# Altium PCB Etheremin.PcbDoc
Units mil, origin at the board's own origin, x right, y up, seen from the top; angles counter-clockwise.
Board outline 6000 x 4000 mil, 2 copper layers (Top Layer, Bottom Layer); 48 components, 40 nets, 135 pads, 0 vias.
Unrouted connection lines stored in the file: 90.
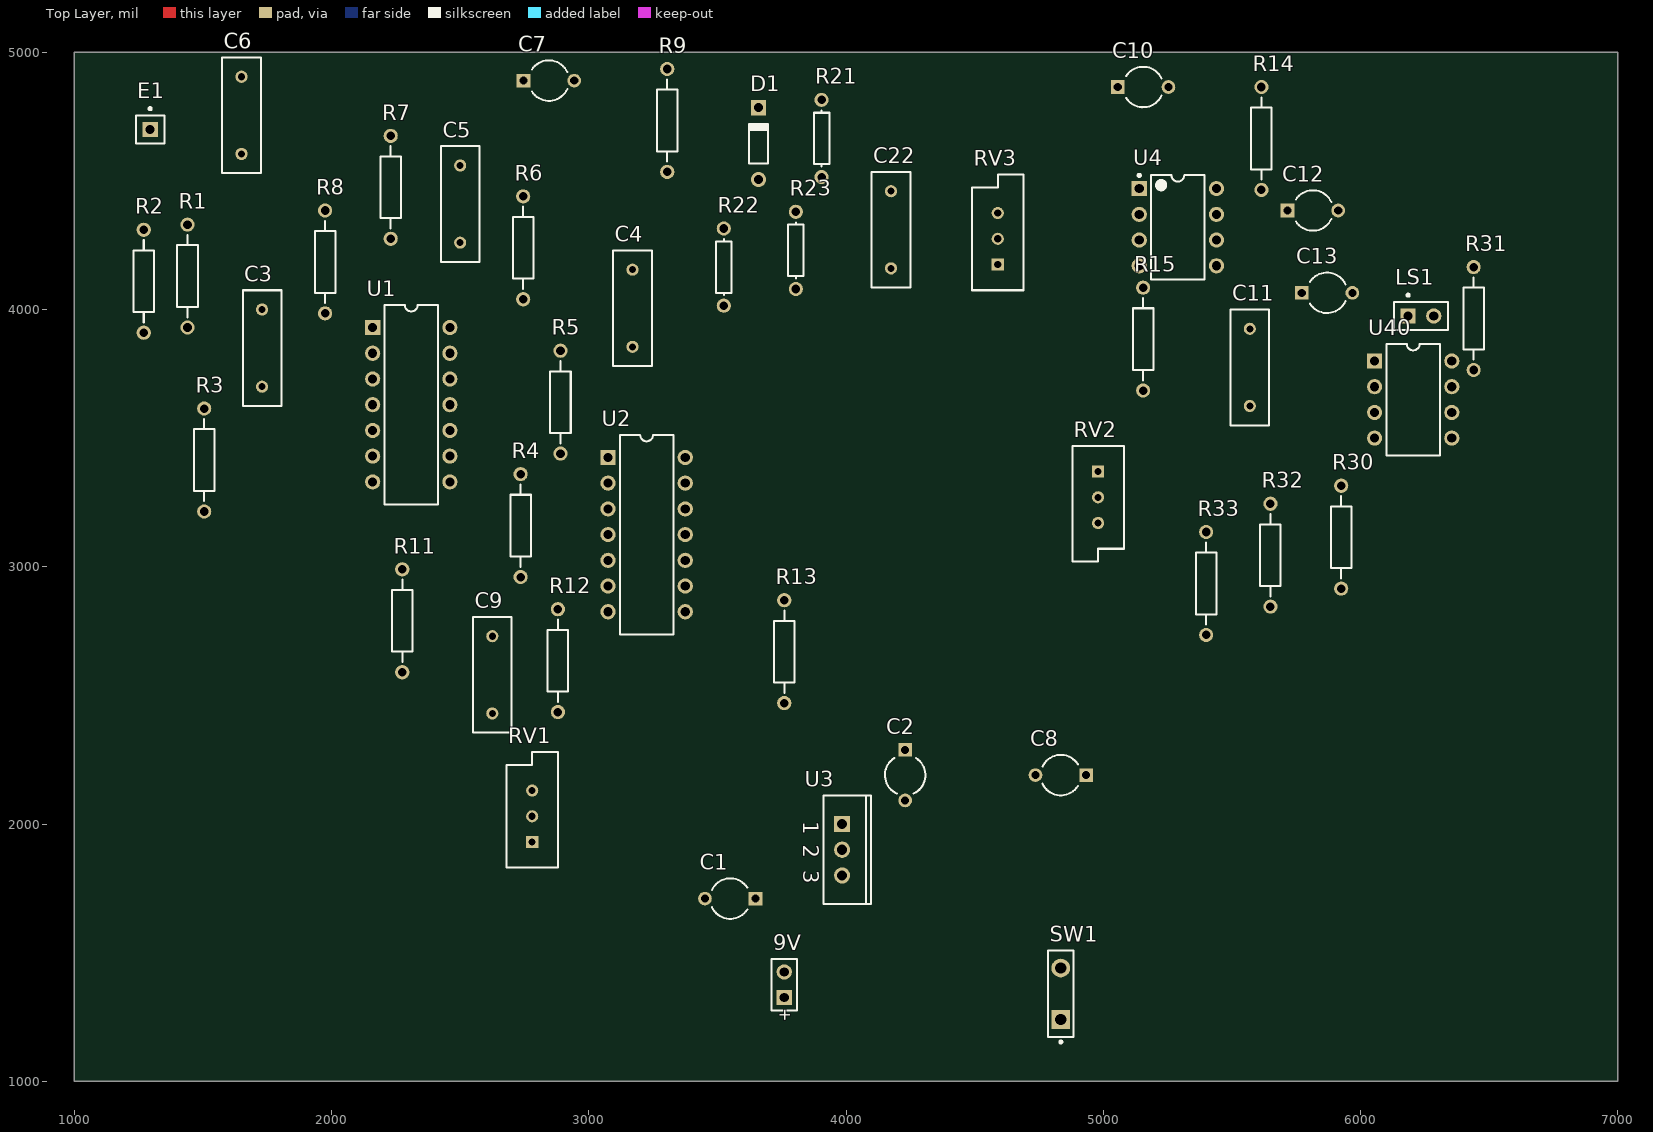
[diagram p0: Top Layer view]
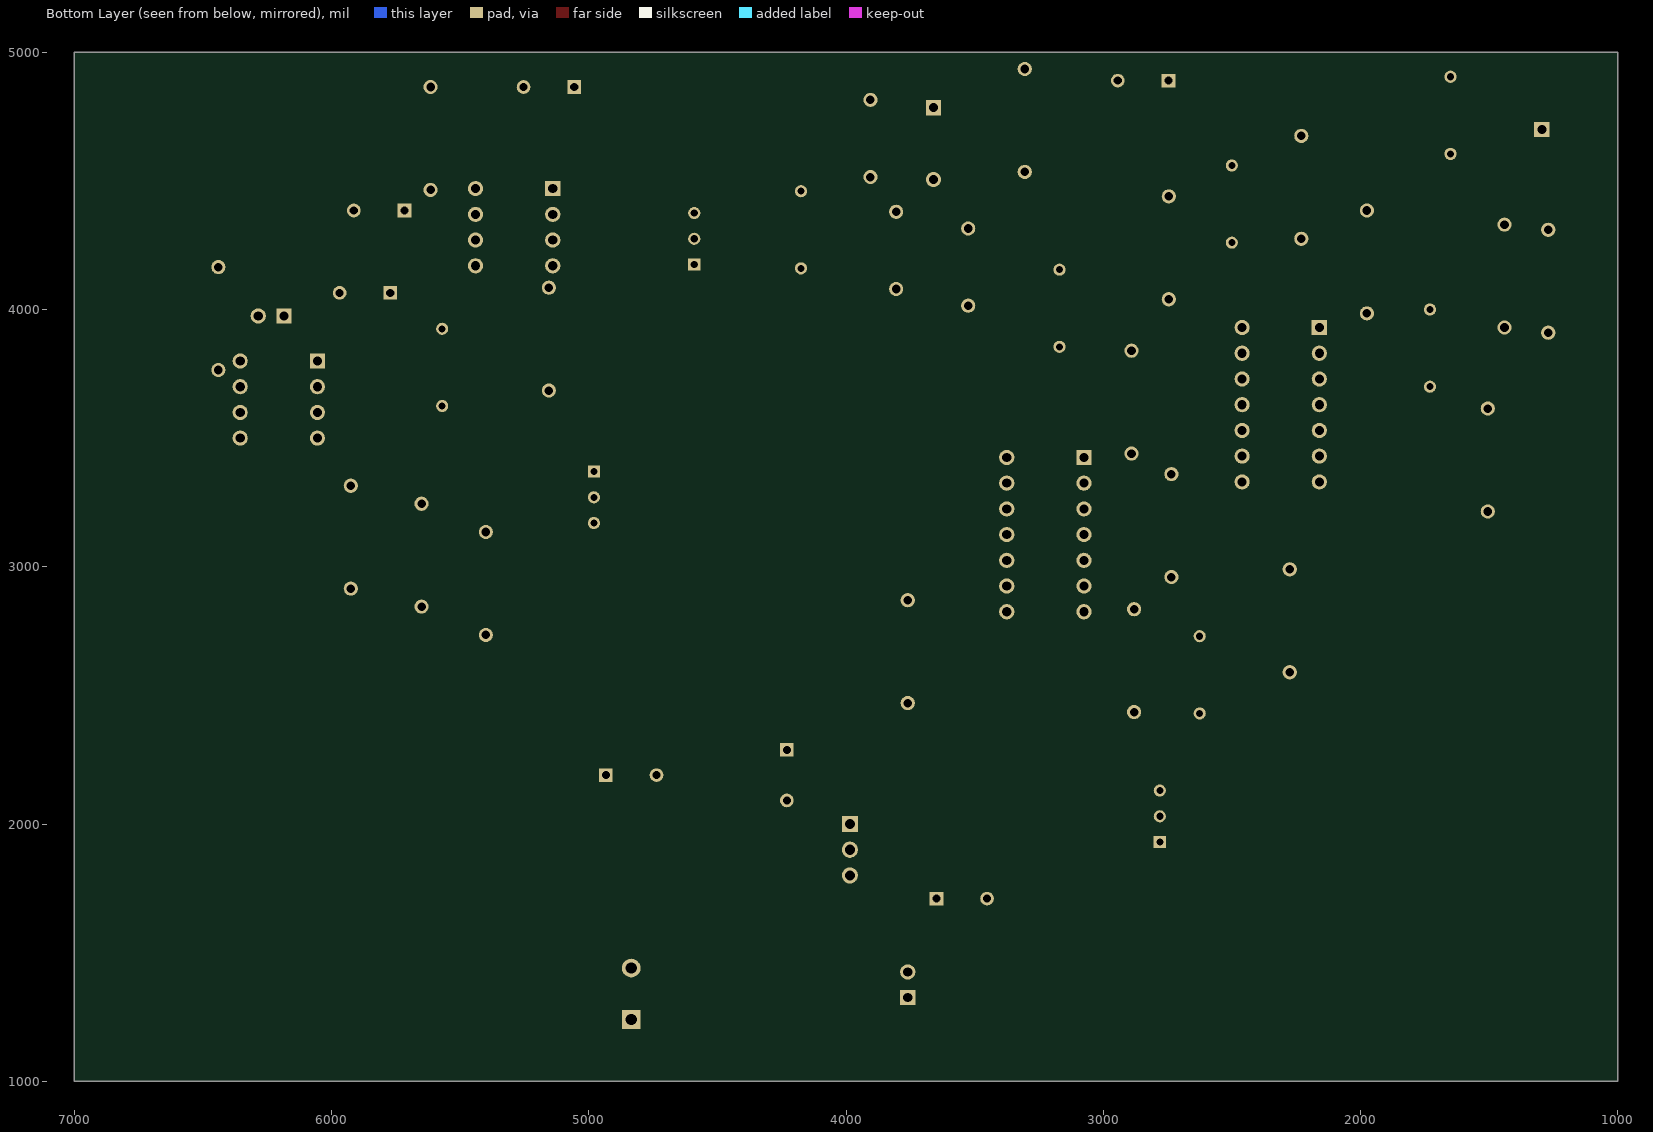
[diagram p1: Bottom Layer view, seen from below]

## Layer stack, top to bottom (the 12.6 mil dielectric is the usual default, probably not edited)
Top Layer: signal copper 1.4
Dielectric: dielectric 12.6, FR-4, Dk 4.8
Bottom Layer: signal copper 1.4

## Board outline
1000,1000 7000,1000 7000,5000 1000,5000

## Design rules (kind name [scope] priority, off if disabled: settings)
Clearance [All] p1: gap=10
PolygonConnect [All] p1: connectstyle=Relief reliefconductorwidth=10 reliefentries=4 polygonreliefangle="90 Angle" airgapwidth=10
RoomDefinition Etheremin [InComponentClass('Etheremin')] p1: confinementstyle=ConfineIn formatcopy=TRUE lockcomponents=FALSE outline 565,65 12140,65 12140,965 565,965
RoutingVias [All] p1: holewidth=28 width=50 viastyle="Through Hole" minholewidth=28 minwidth=50 maxholewidth=28 maxwidth=50
SilkscreenOverComponentPads [All] p1: minsilkscreentomaskgap=10
SolderMaskExpansion [All] p1: expansion=4
Width [All] p1: maxlimit=10 minlimit=10 preferedwidth=10
27 further rules are at their usual default settings.

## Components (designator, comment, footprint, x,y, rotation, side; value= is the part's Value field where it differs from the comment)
9V "Battery" BAT-2 3760,1375 r90 top
C1 "" CAPR5-4X5 3550,1710 r180 top
C2 "" CAPR5-4X5 4230,2190 r270 top
C3 "" RAD-0.3 1730,3850 r90 top
C4 "Cap" RAD-0.3 3170,4005 r90 top
C5 "" RAD-0.3 2500,4410 r90 top
C6 "" RAD-0.3 1650,4755 r90 top
C7 "" CAPR5-4X5 2845,4890 r0 top
C8 "" CAPR5-4X5 4835,2190 r180 top
C9 "" RAD-0.3 2625,2580 r90 top
C10 "" CAPR5-4X5 5155,4865 r0 top
C11 "" RAD-0.3 5570,3775 r90 top
C12 "" CAPR5-4X5 5815,4385 r0 top
C13 "" CAPR5-4X5 5870,4065 r0 top
C22 "Cap" RAD-0.3 4175,4310 r90 top
D1 "Diode 1N4448" DO-35 3660,4645 r90 top
E1 "Antenna" PIN1 1295,4700 r0 top
LS1 "Speaker" PIN2 6185,3975 r0 top
R1 "" AXIAL-0.4 1440,4130 r90 top
R2 "" AXIAL-0.4 1270,4110 r90 top
R3 "" AXIAL-0.4 1505,3415 r90 top
R4 "" AXIAL-0.4 2735,3160 r90 top
R5 "" AXIAL-0.4 2890,3640 r90 top
R6 "" AXIAL-0.4 2745,4240 r90 top
R7 "" AXIAL-0.4 2230,4475 r90 top
R8 "" AXIAL-0.4 1975,4185 r90 top
R9 "" AXIAL-0.4 3305,4735 r90 top
R11 "" AXIAL-0.4 2275,2790 r90 top
R12 "" AXIAL-0.4 2880,2635 r90 top
R13 "" AXIAL-0.4 3760,2670 r270 top
R14 "" AXIAL-0.4 5615,4665 r270 top
R15 "" AXIAL-0.4 5155,3885 r90 top
R21 "Res1" AXIAL-0.3 3905,4665 r270 top
R22 "Res1" AXIAL-0.3 3525,4165 r90 top
R23 "Res1" AXIAL-0.3 3805,4230 r90 top
R30 "" AXIAL-0.4 5925,3115 r270 top
R31 "" AXIAL-0.4 6440,3965 r90 top
R32 "" AXIAL-0.4 5650,3045 r90 top
R33 "" AXIAL-0.4 5400,2935 r90 top
RV1 "" VR5 2780,2030 r90 top
RV2 "" VR5 4980,3270 r270 top
RV3 "" VR5 4590,4275 r90 top
SW1 "On-Off" SPST-2 4835,1340 r90 top
U1 "SN74LS04N" N014 2310,3630 r270 top
U2 "SN74LS04N" N014 3225,3125 r270 top
U3 "LM317KC" KC03 3985,1900 r270 top
U4 "LM386N-3" N08E 5290,4320 r0 top
U40 "LM193N" DIP8 6205,3650 r270 top

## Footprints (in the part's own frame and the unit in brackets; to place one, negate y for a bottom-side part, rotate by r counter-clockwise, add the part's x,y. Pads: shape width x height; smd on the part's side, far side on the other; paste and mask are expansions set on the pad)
AXIAL-0.3 [mm] "Axial Device, Thru-Hole; 2 Leads; 0.3 in Pin Spacing"
  round 1.4 hole 0.85: 1(-3.81,0) 2(3.81,0)
  silkscreen extent -2.77,-0.76 2.77,0.76
AXIAL-0.4 [mm] "Axial Device, Thru-Hole; 2 Leads; 0.4 in Pin Spacing"
  round 1.4 hole 0.85: 1(-5.08,0) 2(5.08,0)
  silkscreen extent -4.06,-1.02 4.06,1.02
BAT-2 [mm] "Battery; 2 Leads"
  rect 1.5x1.5 hole 0.9: 1(-1.27,0)
  round 1.5 hole 0.9: 2(1.27,0)
  silkscreen extent -2.54,-1.27 2.54,1.27
CAPR5-4X5 [mm] "Capacitor; 2 Leads"
  rect 1.35x1.35 hole 0.8: 1(-2.5,0)
  round 1.35 hole 0.8: 2(2.5,0)
  silkscreen extent -1.69,-2 1.82,2
DIP8 [mm] "DIP; 8 Leads; Row Spacing 7.62 mm; Pitch 2.54 mm"
  rect 1.5x1.5 hole 0.9: 1(-3.81,-3.81)
  round 1.5 hole 0.9: 2(-1.27,-3.81) 3(1.27,-3.81) 4(3.81,-3.81) 5(3.81,3.81) 6(1.27,3.81) 7(-1.27,3.81) 8(-3.81,3.81)
  silkscreen extent -5.5,-2.65 5.5,2.65
DO-35 [mm] "Diode, Axial; Body 3.8 x 1.9 mm (LxDia. max), Lead Dia. 0.53 mm (max)"
  round 1.5 hole 0.9: 1(-3.55,0)
  rect 1.5x1.5 hole 0.9: 2(3.55,0)
  silkscreen extent -1.95,-0.95 2.05,0.95
KC03 [mm] "TO, Thru-Hole, Vertical, Heatsink Mounted; 3 In-Line Leads; Pitch 2.54 mm"
  rect 1.6x1.6 hole 1: 1(-2.54,0)
  round 1.6 hole 1: 2(0,0) 3(2.54,0)
  silkscreen extent -5.35,-1.85 5.35,2.85
N08E [mm] "DIP, 8-Leads, Row Spacing 7.62mm, Pitch 2.54mm, Body 9.91x6.35mm"
  rect 1.5x1.5 hole 0.9: 1(-3.81,3.81)
  round 1.5 hole 0.9: 2(-3.81,1.27) 3(-3.81,-1.27) 4(-3.81,-3.81) 5(3.81,-3.81) 6(3.81,-1.27) 7(3.81,1.27) 8(3.81,3.81)
  silkscreen extent -3.93,-5.15 2.65,5.23, body extent -3.6,-5.15 3.6,5.15, height 5.34
N014 [mm] "DIP; 14 Leads; Row Spacing 7.62 mm; Pitch 2.54 mm"
  rect 1.5x1.5 hole 0.9: 1(-7.62,-3.81)
  round 1.5 hole 0.9: 2(-5.08,-3.81) 3(-2.54,-3.81) 4(0,-3.81) 5(2.54,-3.81) 6(5.08,-3.81) 7(7.62,-3.81) 8(7.62,3.81) 9(5.08,3.81) 10(2.54,3.81) 11(0,3.81) 12(-2.54,3.81) 13(-5.08,3.81) 14(-7.62,3.81)
  silkscreen extent -9.85,-2.65 9.85,2.65
PIN1 [mm] "Generic Antenna; 1 Lead"
  rect 1.5x1.5 hole 0.9: 1(0,0)
  silkscreen extent -1.4,-1.4 1.4,2.17
PIN2 [mm] "Photosensitive Diode; 2 Leads"
  rect 1.5x1.5 hole 0.9: 1(0,0)
  round 1.5 hole 0.9: 2(2.54,0)
  silkscreen extent -1.4,-1.4 3.94,2.17
RAD-0.3 [mm] "Radial Cap, Thru-Hole; 2 Leads; 0.3 in Pin Spacing"
  round 1.2 hole 0.7: 1(-3.81,0) 2(3.81,0)
  silkscreen extent -5.71,-1.91 5.71,1.91
SPST-2 [mm] "Switch; 2 Leads"
  rect 1.85x1.85 hole 1.1: 1(-2.54,0)
  round 1.85 hole 1.1: 2(2.54,0)
  silkscreen extent -4.89,-1.27 4.28,1.27
VR5 [mm] "Thru-Hole; 3 Leads"
  rect 1.2x1.2 hole 0.7: 1(-2.54,0)
  round 1.2 hole 0.7: 2(0,0) 3(2.54,0)
  silkscreen extent -5.08,-2.54 6.35,2.54

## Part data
9V: "Multicell Battery"
C1 C2 C7 C8 C10 C12 C13: library part Cap2, "Capacitor"
C3 C5 C6 C9 C11: library part Cap, "Capacitor"
C4 C22: "Capacitor"
D1: "High Conductance Fast Diode"
E1: "Generic Antenna"
LS1: "Loudspeaker"
R1 R2 R3 R4 R5 R6 R7 R8 R9 R11 R12 R13 R14 R15 R30 R31 R32 R33: library part Res2, "Resistor"
R21 R22 R23: "Resistor"
RV1 RV2 RV3: library part RPot, "Potentiometer"
SW1: library part SW-PB, "Switch"
U1 U2: "Hex Inverter"
U3: "3-Terminal Adjustable Regulator"
U4: "Low Voltage Audio Power Amplifier"
U40: "Low-Power Dual Voltage Comparator"

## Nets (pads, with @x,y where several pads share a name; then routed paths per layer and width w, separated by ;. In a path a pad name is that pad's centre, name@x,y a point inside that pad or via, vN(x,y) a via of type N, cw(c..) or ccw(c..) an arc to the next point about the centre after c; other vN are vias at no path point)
GND: 9V.2 C1.2 C2.2 C5.1 C8.2 C12.2 C22.1 LS1.2 R13.2 R15.2 R22.1 R23.1 R32.1 RV3.1 U1.7 U2.7 U2.9 U3.1 U4.2 U4.4 U40.8
Net9V_1: 9V.1 SW1.1
NetC1_1: C1.1 SW1.2 U3.3
NetC3_1: C3.1 U1.4 U1.5
NetC3_2: C3.2 E1.1 R1.2 R2.2
NetC4_1: C4.1 R5.1 U1.8
NetC4_2: C4.2 R6.1
NetC5_2: C5.2 R6.2 R7.2
NetC6_1: C6.1 R7.1 R8.2 U1.11 U1.13
NetC6_2: C6.2 C7.1 R8.1 U1.10 U1.12
NetC7_2: C7.2 R9.2
NetC8_1: C8.1 RV2.3
NetC9_1: C9.1 R11.1 RV1.1 RV1.3
NetC9_2: C9.2 U2.4 U2.5
NetC10_1: C10.1 U4.1
NetC10_2: C10.2 R14.1
NetC11_1: C11.1 R15.1
NetC11_2: C11.2 C13.1 U4.5
NetC12_1: C12.1 U4.7
NetC13_2: C13.2 R31.2
NetC22_2: C22.2 R21.2 R23.2 RV3.2
NetD1_1: D1.1 R9.1 R22.2
NetD1_2: D1.2 R21.1
NetLS1_1: LS1.1 R33.1 U40.1
NetR1_1: R1.1 U1.1
NetR2_1: R2.1 U1.2 U1.3
NetR3_1: R3.1 R4.1 R5.2 U1.9
NetR3_2: R3.2 U1.6
NetR4_2: R4.2 U2.6
NetR11_2: R11.2 U2.1
NetR12_1: R12.1 RV1.2
NetR12_2: R12.2 U2.2 U2.3
NetR13_1: R13.1 RV2.1
NetR14_2: R14.2 U4.8
NetR30_1: R30.1 R31.1 U40.3
NetR32_2: R32.2 R33.2 U40.2
NetRV3_3: RV3.3 U4.3
NetU2_8: U2.8 U2.11
NetU2_10: U2.10 U2.13
VCC: C2.1 RV2.2 U1.14 U2.14 U3.2 U4.6 U40.4
pads on no net: R30.2 U2.12 U40.5 U40.6 U40.7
